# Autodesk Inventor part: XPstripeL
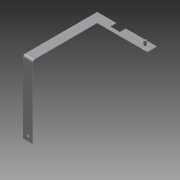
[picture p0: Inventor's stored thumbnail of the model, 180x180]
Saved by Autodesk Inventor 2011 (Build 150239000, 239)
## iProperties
Created: 2014-11
Part Number: XPstripeL
Document SubType Name: Modeling
Designer: Evgeny
Density: 1 g/cm^3
Author: Evgeny
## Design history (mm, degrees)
sketch "Эскиз1"
  geometry: L1 (17, 28)-(17, 32); L2 (-4, 28)-(-4, 1); L3 (-4, 1)-(-8, 1); L4 (-8, 32)-(-8, 1); L5 (0, 29.5)-(4, 29.5); L6 (0, 29.5)-(0, 32); L7 (4, 29.5)-(4, 32); L8 (17, 32)-(4, 32); L9 (0, 32)-(-8, 32); L10 (-4, 28)-(17, 28); C1 r 0.5 at (14, 30); 1 further point
  constraints: 20 end point, 3 perpendicular, 2 horizontal, 2 parallel, 1 centre point
  dimensions: "d1" = 25 distance between parallel lines of L4 L1; "d2" = 4 distance between parallel lines of L2 L4; "d3" = 1 diameter of C1; "d4" = 3 distance from line of L1 C1.centre; "d26" = 4 distance between parallel lines of L10 L8; "d27" = 13 distance between parallel lines of L7 L1; "d28" = 4 distance between parallel lines of L6 L7; "d29" = 1.5 distance between parallel lines of L10 L5
extrude "Выдавливание1" new body sketch "Эскиз1" distance "d10" = 0.25; taper "d11" = 0 deg
sketch "Эскиз3"
  geometry: L1 (8, 1)-(8, 32) reference; L2 (4, 1)-(8, 1); L3 (8, 1)-(8, 1.25); L4 (8, 1.25)-(4, 1.25); L5 (4, 1.25)-(4, 1); 1 further point
  constraints: 8 end point, 2 parallel, 1 horizontal, 1 perpendicular, 1 point on line
  dimensions: "d30" = 0.25 distance between parallel lines of L4 L2
extrude "Выдавливание3" join sketch "Эскиз3" distance "d31" = 30; taper "d32" = 0 deg
fillet "Сопряжение3" dims "d33" = 0.75
fillet "Сопряжение4" dims "d34" = 1
hole "Отверстие2" diameter "d37" = 1; stored, may be unused: countersink angle "d41" = 90 deg, drill point angle "d43" = 118 deg; dims "d35" = 2, "d36" = 2, "d38" = 6, "d39" = 4, "d40" = 2, "d42" = 1
extrude "Выдавливание4" join sketch "Эскиз1" distance "d44" = 2; taper "d45" = 0 deg; dims "d46" = 0.25, "d47" = 0
node "Твердое тело1"
other parameters: "d0" = 31, "d5" = 4, "d6" = 2, "d9" = 1.5
